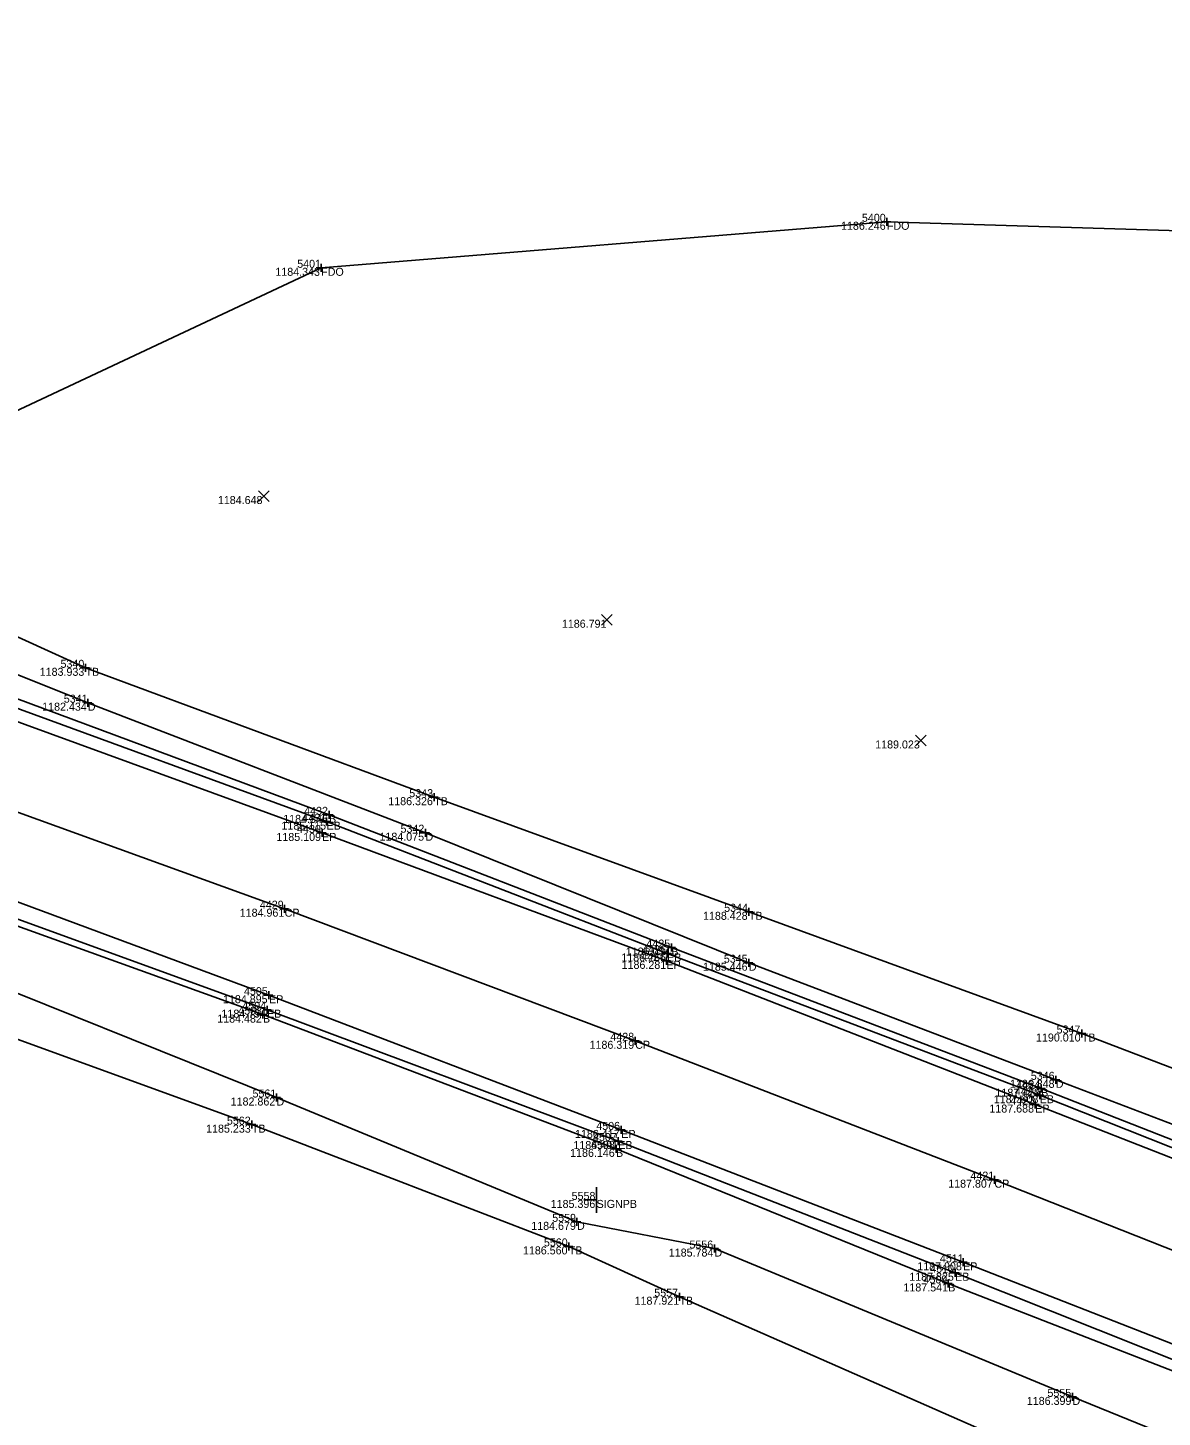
# Model space of a CAD drawing. Extents: x 2044996 to 2050343, y 455232 to 458054.
# Drawn here: x 2047056.8 to 2047198.7, y 457137.8 to 457311.5 of the extents above; entities that cross this region are included whole.
import ezdxf

# ---------------------------------------------------------------- set-up
doc = ezdxf.new("R2010")
doc.units = 0
for name, color, linetype in [('Default', 7, 'Continuous'), ('DR_X_Ditch', 7, 'Continuous'), ('DR_X_Elev_Flow', 7, 'Continuous'), ('DT_X_Contour_Minor', 7, 'Continuous'), ('DT_X_Contour_Text', 7, 'Continuous'), ('DT_X_Spot_Elev', 7, 'Continuous'), ('DT_X_Triangles', 7, 'Continuous'), ('DT_X_Void', 7, 'Continuous'), ('PV_X_COP', 7, 'Continuous'), ('PV_X_EOP', 7, 'Continuous'), ('PV_X_Shoulder_Aggregate', 7, 'Continuous'), ('SN_X_Public', 7, 'Continuous'), ('SV_X_Break_Lines', 7, 'Continuous'), ('SV_X_Top_of_Bank', 7, 'Continuous')]:
    doc.layers.add(name, color=color, linetype=linetype)

msp = doc.modelspace()

# ---------------------------------------------------------------- linework, layer by layer
at = {"layer": 'Default'}
msp.add_lwpolyline([(2047593.97, 457240.01), (2047493.12, 457201.08), (2047446.62, 457210.33), (2047381.19, 457253.8), (2047314.69, 457278.12), (2047219.94, 457285.5), (2047164.25, 457287.21), (2047093.51, 457281.46), (2047021.48, 457247.68)], dxfattribs=at)
at = {"layer": 'DR_X_Ditch'}
for points in [[(2046652.09, 457304.73), (2046697.72, 457300.76), (2046749.85, 457295.15), (2046773.58, 457293.27), (2046813.42, 457287.29), (2046865.63, 457279.49), (2046913.29, 457272.1), (2046945.7, 457266), (2046955.45, 457263.32), (2046957.87, 457262.51), (2047003.84, 457250.36), (2047016.8, 457245.89), (2047017.67, 457245.73), (2047064.32, 457227.1), (2047106.55, 457210.85), (2047146.99, 457194.6), (2047185.37, 457179.96), (2047230.91, 457162.64)], [(2047543.3, 457005.16), (2047510.9, 457017.43), (2047468.96, 457033.16), (2047427.45, 457048.41), (2047415.45, 457054.04), (2047370.9, 457068.47), (2047328.33, 457085.8), (2047280.45, 457104.21), (2047241.61, 457118.3), (2047187.46, 457140.33), (2047142.69, 457158.87), (2047125.5, 457162.21), (2047087.92, 457177.75), (2047044.55, 457195.18), (2046997.32, 457212.04), (2046988.97, 457212.79)]]:
    msp.add_lwpolyline(points, dxfattribs=at)
at = {"layer": 'DR_X_Elev_Flow'}
for p, q in [((2047163.75, 457287.21), (2047164.75, 457287.21)), ((2047164.25, 457287.71), (2047164.25, 457286.71)), ((2047164.25, 457287.21), (2047164.25, 457287.21)), ((2047093.51, 457281.96), (2047093.51, 457280.96)), ((2047093.01, 457281.46), (2047094.01, 457281.46)), ((2047093.51, 457281.46), (2047093.51, 457281.46))]:
    msp.add_line(p, q, dxfattribs=at)
at = {"layer": 'DT_X_Spot_Elev'}
for p, q in [((2047085.66, 457252.26), (2047086.99, 457253.6)), ((2047085.66, 457253.6), (2047086.99, 457252.26)), ((2047128.55, 457236.8), (2047129.89, 457238.14)), ((2047128.55, 457238.14), (2047129.89, 457236.8)), ((2047167.85, 457221.71), (2047169.18, 457223.04)), ((2047167.85, 457223.04), (2047169.18, 457221.71))]:
    msp.add_line(p, q, dxfattribs=at)
at = {"layer": 'DT_X_Void'}
for p, q in [((2047063.53, 457231.46), (2047064.53, 457231.46)), ((2047064.03, 457231.96), (2047064.03, 457230.96)), ((2047064.03, 457231.46), (2047064.03, 457231.46)), ((2047063.82, 457227.1), (2047064.82, 457227.1)), ((2047064.32, 457227.6), (2047064.32, 457226.6)), ((2047064.32, 457227.1), (2047064.32, 457227.1)), ((2047107.63, 457215.79), (2047107.63, 457214.79)), ((2047107.13, 457215.29), (2047108.13, 457215.29)), ((2047107.63, 457215.29), (2047107.63, 457215.29)), ((2047093.68, 457212.23), (2047094.68, 457212.23)), ((2047093.99, 457213.08), (2047094.99, 457213.08)), ((2047094.18, 457212.73), (2047094.18, 457211.73)), ((2047094.18, 457212.23), (2047094.18, 457212.23)), ((2047094.49, 457213.58), (2047094.49, 457212.58)), ((2047094.49, 457213.08), (2047094.49, 457213.08)), ((2047093.12, 457210.82), (2047094.12, 457210.82)), ((2047093.62, 457211.32), (2047093.62, 457210.32)), ((2047093.62, 457210.82), (2047093.62, 457210.82)), ((2047106.05, 457210.85), (2047107.05, 457210.85)), ((2047106.55, 457211.35), (2047106.55, 457210.35)), ((2047106.55, 457210.85), (2047106.55, 457210.85)), ((2047088.94, 457201.85), (2047088.94, 457200.85)), ((2047088.44, 457201.35), (2047089.44, 457201.35)), ((2047088.94, 457201.35), (2047088.94, 457201.35)), ((2047146.49, 457200.96), (2047147.49, 457200.96)), ((2047146.99, 457201.46), (2047146.99, 457200.46)), ((2047146.99, 457200.96), (2047146.99, 457200.96)), ((2047137.31, 457196.99), (2047137.31, 457195.99)), ((2047136.19, 457194.83), (2047137.19, 457194.83)), ((2047136.27, 457195.76), (2047137.27, 457195.76)), ((2047136.69, 457195.33), (2047136.69, 457194.33)), ((2047136.69, 457194.83), (2047136.69, 457194.83)), ((2047136.77, 457196.26), (2047136.77, 457195.26)), ((2047136.77, 457195.76), (2047136.77, 457195.76)), ((2047136.81, 457196.49), (2047137.81, 457196.49)), ((2047137.31, 457196.49), (2047137.31, 457196.49)), ((2047146.99, 457195.1), (2047146.99, 457194.1)), ((2047146.49, 457194.6), (2047147.49, 457194.6)), ((2047146.99, 457194.6), (2047146.99, 457194.6)), ((2047086.48, 457190.54), (2047087.48, 457190.54)), ((2047086.98, 457191.04), (2047086.98, 457190.04)), ((2047086.98, 457190.54), (2047086.98, 457190.54)), ((2047085.73, 457188.11), (2047086.73, 457188.11)), ((2047086.23, 457188.61), (2047086.23, 457187.61)), ((2047086.23, 457188.11), (2047086.23, 457188.11)), ((2047086.24, 457188.73), (2047087.24, 457188.73)), ((2047086.74, 457189.23), (2047086.74, 457188.23)), ((2047086.74, 457188.73), (2047086.74, 457188.73)), ((2047188.63, 457186.25), (2047188.63, 457185.25)), ((2047132.28, 457184.84), (2047133.28, 457184.84)), ((2047132.78, 457185.34), (2047132.78, 457184.34)), ((2047132.78, 457184.84), (2047132.78, 457184.84)), ((2047188.13, 457185.75), (2047189.13, 457185.75)), ((2047188.63, 457185.75), (2047188.63, 457185.75)), ((2047183.55, 457179.36), (2047183.55, 457178.36)), ((2047184.87, 457179.96), (2047185.87, 457179.96)), ((2047185.37, 457180.46), (2047185.37, 457179.46)), ((2047185.37, 457179.96), (2047185.37, 457179.96)), ((2047087.42, 457177.75), (2047088.42, 457177.75)), ((2047087.92, 457178.25), (2047087.92, 457177.25)), ((2047087.92, 457177.75), (2047087.92, 457177.75)), ((2047182.86, 457178.03), (2047183.86, 457178.03)), ((2047183.05, 457178.86), (2047184.05, 457178.86)), ((2047183.36, 457178.53), (2047183.36, 457177.53)), ((2047183.36, 457178.03), (2047183.36, 457178.03)), ((2047183.55, 457178.86), (2047183.55, 457178.86)), ((2047182.3, 457176.87), (2047183.3, 457176.87)), ((2047182.8, 457177.37), (2047182.8, 457176.37)), ((2047182.8, 457176.87), (2047182.8, 457176.87)), ((2047084.34, 457174.36), (2047085.34, 457174.36)), ((2047084.84, 457174.86), (2047084.84, 457173.86)), ((2047084.84, 457174.36), (2047084.84, 457174.36)), ((2047131.03, 457174.2), (2047131.03, 457173.2)), ((2047130.16, 457172.31), (2047131.16, 457172.31)), ((2047130.53, 457173.7), (2047131.53, 457173.7)), ((2047130.66, 457172.81), (2047130.66, 457171.81)), ((2047130.66, 457172.31), (2047130.66, 457172.31)), ((2047131.03, 457173.7), (2047131.03, 457173.7)), ((2047129.88, 457171.33), (2047130.88, 457171.33)), ((2047130.38, 457171.83), (2047130.38, 457170.83)), ((2047130.38, 457171.33), (2047130.38, 457171.33)), ((2047177.2, 457167.48), (2047178.2, 457167.48)), ((2047177.7, 457167.98), (2047177.7, 457166.98)), ((2047177.7, 457167.48), (2047177.7, 457167.48)), ((2047125, 457162.21), (2047126, 457162.21)), ((2047125.5, 457162.71), (2047125.5, 457161.71)), ((2047125.5, 457162.21), (2047125.5, 457162.21)), ((2047123.98, 457159.14), (2047124.98, 457159.14)), ((2047124.48, 457159.64), (2047124.48, 457158.64)), ((2047124.48, 457159.14), (2047124.48, 457159.14)), ((2047142.19, 457158.87), (2047143.19, 457158.87)), ((2047142.69, 457159.37), (2047142.69, 457158.37)), ((2047142.69, 457158.87), (2047142.69, 457158.87)), ((2047173.28, 457157.15), (2047174.28, 457157.15)), ((2047173.78, 457157.65), (2047173.78, 457156.65)), ((2047173.78, 457157.15), (2047173.78, 457157.15)), ((2047171.93, 457155.01), (2047171.93, 457154.01)), ((2047172.29, 457155.85), (2047173.29, 457155.85)), ((2047172.79, 457156.35), (2047172.79, 457155.35)), ((2047172.79, 457155.85), (2047172.79, 457155.85)), ((2047138.32, 457153.35), (2047138.32, 457152.35)), ((2047171.43, 457154.51), (2047172.43, 457154.51)), ((2047171.93, 457154.51), (2047171.93, 457154.51)), ((2047137.82, 457152.85), (2047138.82, 457152.85)), ((2047138.32, 457152.85), (2047138.32, 457152.85)), ((2047186.96, 457140.33), (2047187.96, 457140.33)), ((2047187.46, 457140.83), (2047187.46, 457139.83)), ((2047187.46, 457140.33), (2047187.46, 457140.33))]:
    msp.add_line(p, q, dxfattribs=at)
at = {"layer": 'PV_X_COP'}
msp.add_lwpolyline([(2047612.39, 456999.11), (2047580.09, 457011.53), (2047538.37, 457027.53), (2047496.01, 457043.83), (2047451.82, 457060.1), (2047409.77, 457076.51), (2047364.77, 457093.97), (2047313.94, 457114.01), (2047268.54, 457131.55), (2047222.12, 457149.92), (2047177.7, 457167.48), (2047132.78, 457184.84), (2047088.94, 457201.35), (2047045.02, 457217.22), (2047000.47, 457231.97), (2046961.14, 457242.7), (2046914.32, 457253.6), (2046869.82, 457261.81), (2046824.05, 457268.96), (2046778.68, 457274.62), (2046733.92, 457279.83), (2046684.61, 457284.92), (2046649.61, 457288.12)], dxfattribs=at)
at = {"layer": 'PV_X_EOP'}
for p, q in [((2047093.62, 457210.82), (2047049.38, 457226.95)), ((2047136.69, 457194.83), (2047093.62, 457210.82)), ((2047041.61, 457207.34), (2047086.98, 457190.54)), ((2047182.8, 457176.87), (2047136.69, 457194.83)), ((2047086.98, 457190.54), (2047131.03, 457173.7)), ((2047226.47, 457159.73), (2047182.8, 457176.87)), ((2047131.03, 457173.7), (2047173.78, 457157.15)), ((2047173.78, 457157.15), (2047217.52, 457140.08))]:
    msp.add_line(p, q, dxfattribs=at)
at = {"layer": 'PV_X_Shoulder_Aggregate'}
for p, q in [((2047094.18, 457212.23), (2047049.75, 457228.48)), ((2047136.77, 457195.76), (2047094.18, 457212.23)), ((2047041.53, 457205.14), (2047086.74, 457188.73)), ((2047183.36, 457178.03), (2047136.77, 457195.76)), ((2047086.74, 457188.73), (2047130.66, 457172.31)), ((2047227.14, 457160.66), (2047183.36, 457178.03)), ((2047130.66, 457172.31), (2047172.79, 457155.85)), ((2047172.79, 457155.85), (2047216.98, 457138.21))]:
    msp.add_line(p, q, dxfattribs=at)
at = {"layer": 'SN_X_Public'}
for p, q in [((2047127.95, 457166.55), (2047127.95, 457163.35)), ((2047127.95, 457164.95), (2047126.35, 457164.95))]:
    msp.add_line(p, q, dxfattribs=at)
at = {"layer": 'SV_X_Break_Lines'}
for points in [[(2047227.37, 457161.69), (2047183.55, 457178.86), (2047137.31, 457196.49), (2047094.49, 457213.08), (2047049.99, 457229.63), (2047005.1, 457243.65), (2046965.33, 457255.5), (2046918.59, 457265.88), (2046873.66, 457274.63), (2046827.67, 457281.56), (2046780.24, 457288.39), (2046735.28, 457292.81), (2046686.23, 457298.46), (2046651.06, 457301.99)], [(2046644.99, 457274.79), (2046684.79, 457271.32), (2046731.45, 457265.98), (2046776.36, 457261.92), (2046820.97, 457255.96), (2046865.17, 457248.93), (2046910.62, 457240.57), (2046953.49, 457230.48), (2046996.08, 457218.34), (2047041.05, 457204.36), (2047086.23, 457188.11), (2047130.38, 457171.33), (2047171.93, 457154.51), (2047216.75, 457137.04), (2047260.77, 457120.17), (2047304.38, 457102.94), (2047349.36, 457085.13), (2047391.24, 457069.28), (2047438.05, 457051.14), (2047480.2, 457035.91), (2047522.53, 457019.68), (2047543.14, 457011.06)]]:
    msp.add_lwpolyline(points, dxfattribs=at)
at = {"layer": 'SV_X_Top_of_Bank'}
for points in [[(2046651.93, 457311.46), (2046700.58, 457305.72), (2046746.85, 457300.37), (2046773.13, 457296.21), (2046810.21, 457291.65), (2046866.31, 457282.87), (2046913.13, 457276.05), (2046946.87, 457270.5), (2046956.84, 457268.66), (2047005.28, 457255.73), (2047019.97, 457251.51), (2047064.03, 457231.46), (2047107.63, 457215.29), (2047146.99, 457200.96), (2047188.63, 457185.75), (2047229.81, 457169.99), (2047277.5, 457150.03), (2047328.36, 457129.78), (2047359.21, 457118.11), (2047442.14, 457085.97), (2047488.03, 457067.35), (2047530.83, 457050.42), (2047563.67, 457038.95)], [(2047542.15, 457001.74), (2047509.52, 457012.3), (2047466.73, 457029.21), (2047424.59, 457044.27), (2047411.67, 457048.03), (2047368.41, 457063.9), (2047324.9, 457081.08), (2047276.68, 457098.42), (2047234.84, 457112.37), (2047186.92, 457131.46), (2047138.32, 457152.85), (2047124.48, 457159.14), (2047084.84, 457174.36), (2047041.82, 457189.99), (2046999.84, 457207.19), (2046987.02, 457211.13)]]:
    msp.add_lwpolyline(points, dxfattribs=at)

# ---------------------------------------------------------------- texts
at = {"layer": 'DT_X_Contour_Minor'}
for s, p in [('1186.246', (2047158.52, 457286.21)), ('1184.343', (2047087.78, 457280.46)), ('1184.648', (2047080.59, 457251.93)), ('1186.791', (2047123.61, 457236.47)), ('1183.933', (2047058.31, 457230.46)), ('1182.434', (2047058.62, 457226.1)), ('1189.023', (2047162.79, 457221.38)), ('1186.326', (2047101.9, 457214.29)), ('1185.115', (2047088.54, 457211.23)), ('1184.846', (2047088.76, 457212.08)), ('1185.109', (2047087.91, 457209.82)), ('1184.075', (2047100.8, 457209.85)), ('1184.961', (2047083.32, 457200.35)), ('1188.428', (2047141.26, 457199.96)), ('1186.266', (2047131.04, 457194.76)), ('1186.281', (2047131.08, 457193.83)), ('1186.034', (2047131.6, 457195.49)), ('1185.446', (2047141.25, 457193.6)), ('1184.895', (2047081.23, 457189.54)), ('1184.482', (2047080.51, 457187.11)), ('1184.794', (2047081.04, 457187.73)), ('1186.319', (2047127.07, 457183.84)), ('1190.010', (2047182.9, 457184.75)), ('1186.848', (2047179.64, 457178.96)), ('1182.862', (2047082.19, 457176.75)), ('1187.608', (2047177.62, 457177.03)), ('1187.423', (2047177.83, 457177.86)), ('1187.688', (2047177.07, 457175.87)), ('1185.233', (2047079.12, 457173.36)), ('1186.401', (2047125.05, 457171.31)), ('1186.417', (2047125.25, 457172.7)), ('1186.146', (2047124.64, 457170.33)), ('1187.807', (2047171.92, 457166.48)), ('1185.396', (2047122.21, 457163.95)), ('1184.679', (2047119.78, 457161.21)), ('1186.560', (2047118.74, 457158.14)), ('1185.784', (2047136.98, 457157.87)), ('1187.908', (2047168.05, 457156.15)), ('1187.825', (2047167.05, 457154.85)), ('1187.541', (2047166.32, 457153.51)), ('1187.921', (2047132.7, 457151.85)), ('1186.399', (2047181.75, 457139.33))]:
    msp.add_text(s, height=1, dxfattribs=at).set_placement(p)
at = {"layer": 'DT_X_Contour_Text'}
for s, p in [('FDO', (2047164.25, 457286.21)), ('FDO', (2047093.51, 457280.46)), ('TB', (2047064.03, 457230.46)), ('D', (2047064.32, 457226.1)), ('TB', (2047107.63, 457214.29)), ('EB', (2047094.18, 457211.23)), ('B', (2047094.49, 457212.08)), ('EP', (2047093.62, 457209.82)), ('D', (2047106.55, 457209.85)), ('CP', (2047088.94, 457200.35)), ('TB', (2047146.99, 457199.96)), ('EP', (2047136.69, 457193.83)), ('EB', (2047136.77, 457194.76)), ('B', (2047137.31, 457195.49)), ('D', (2047146.99, 457193.6)), ('EP', (2047086.98, 457189.54)), ('B', (2047086.23, 457187.11)), ('EB', (2047086.74, 457187.73)), ('CP', (2047132.78, 457183.84)), ('TB', (2047188.63, 457184.75)), ('D', (2047185.37, 457178.96)), ('D', (2047087.92, 457176.75)), ('EB', (2047183.36, 457177.03)), ('B', (2047183.55, 457177.86)), ('EP', (2047182.8, 457175.87)), ('TB', (2047084.84, 457173.36)), ('EB', (2047130.66, 457171.31)), ('EP', (2047131.03, 457172.7)), ('B', (2047130.38, 457170.33)), ('CP', (2047177.7, 457166.48)), ('SIGNPB', (2047127.95, 457163.95)), ('D', (2047125.5, 457161.21)), ('TB', (2047124.48, 457158.14)), ('D', (2047142.69, 457157.87)), ('EP', (2047173.78, 457156.15)), ('EB', (2047172.79, 457154.85)), ('B', (2047171.93, 457153.51)), ('TB', (2047138.32, 457151.85)), ('D', (2047187.46, 457139.33))]:
    msp.add_text(s, height=1, dxfattribs=at).set_placement(p)
at = {"layer": 'DT_X_Triangles'}
for s, p in [('5400', (2047161.13, 457287.21)), ('5401', (2047090.51, 457281.46)), ('5340', (2047060.91, 457231.46)), ('5341', (2047061.32, 457227.1)), ('5343', (2047104.53, 457215.29)), ('4432', (2047091.38, 457213.08)), ('4431', (2047091.18, 457212.23)), ('4430', (2047090.5, 457210.82)), ('5342', (2047103.43, 457210.85)), ('4429', (2047085.84, 457201.35)), ('5344', (2047143.9, 457200.96)), ('4426', (2047133.65, 457195.76)), ('4425', (2047134.18, 457196.49)), ('4427', (2047133.53, 457194.83)), ('5345', (2047143.86, 457194.6)), ('4505', (2047083.85, 457190.54)), ('4504', (2047083.65, 457188.73)), ('4503', (2047083.13, 457188.11)), ('5347', (2047185.47, 457185.75)), ('4428', (2047129.67, 457184.84)), ('5346', (2047182.25, 457179.96)), ('4424', (2047180.46, 457178.86)), ('5561', (2047084.92, 457177.75)), ('4422', (2047179.69, 457176.87)), ('4423', (2047180.25, 457178.03)), ('5562', (2047081.72, 457174.36)), ('4506', (2047127.91, 457173.7)), ('4508', (2047127.26, 457171.33)), ('4507', (2047127.5, 457172.31)), ('4421', (2047174.7, 457167.48)), ('5558', (2047124.83, 457164.95)), ('5559', (2047122.4, 457162.21)), ('5560', (2047121.36, 457159.14)), ('5556', (2047139.56, 457158.87)), ('4510', (2047169.67, 457155.85)), ('4511', (2047170.88, 457157.15)), ('4509', (2047168.83, 457154.51)), ('5557', (2047135.16, 457152.85)), ('5555', (2047184.33, 457140.33))]:
    msp.add_text(s, height=1, dxfattribs=at).set_placement(p)

doc.saveas('drawing.dxf')
